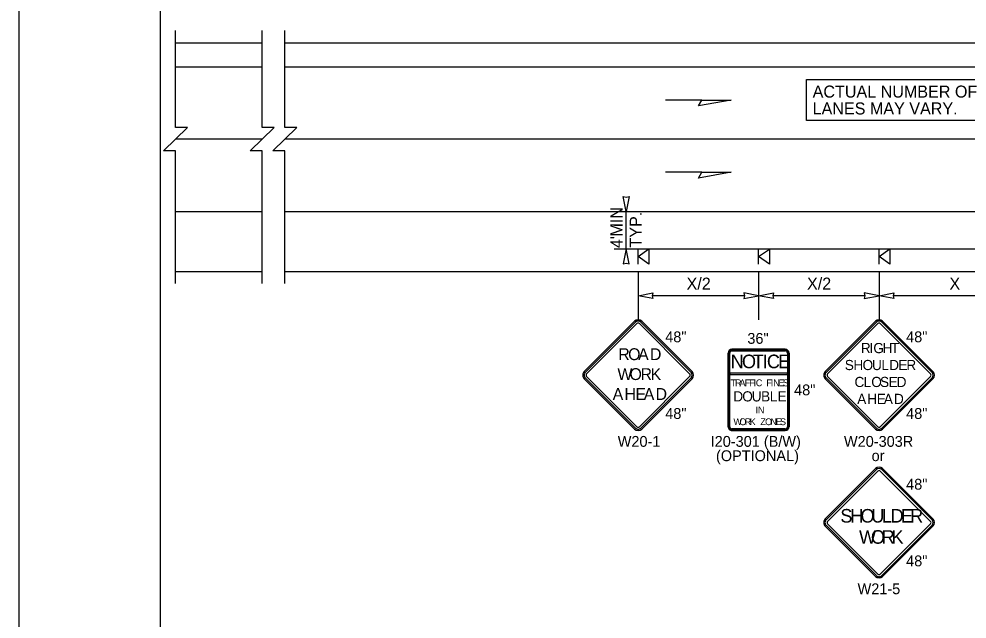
# Model space of a CAD drawing. Extents: x 99999.1 to 100055.7, y 99995 to 100013.2.
# Drawn here: x 99999.06 to 100005.36, y 100002.93 to 100006.91 of the extents above; entities that cross this region are included whole.
import ezdxf

# ---------------------------------------------------------------- set-up
doc = ezdxf.new("R2010")
doc.units = 0
for name, color, linetype in [('RD_ED_ShoulderPavedEdge', 7, 'Continuous'), ('RD_MK_LineEdgeWhite', 7, 'Continuous'), ('RD_MK_LineEdgeYellow', 7, 'Continuous'), ('RD_MK_LineLane', 7, 'Continuous'), ('SH_GI_PlotLimits', 7, 'Continuous'), ('SH_GI_SheetBorder', 7, 'Continuous'), ('SH_TI_Tables', 7, 'Continuous'), ('TR_SN_ConstructionSigns', 7, 'Continuous'), ('TR_WZ_PortableSignMountBlk-Org', 7, 'Continuous'), ('TR_WZ_PortableSignMountBlk-Wht', 7, 'Continuous'), ('TR_WZ_WorkZoneDetails', 7, 'Continuous'), ('TR_WZ_WorkZoneTextCurrent', 7, 'Continuous')]:
    doc.layers.add(name, color=color, linetype=linetype)

msp = doc.modelspace()

# ---------------------------------------------------------------- linework, layer by layer
at = {"layer": 'RD_ED_ShoulderPavedEdge'}
for p, q in [((100000.1016, 100006.7557), (100000.6783, 100006.7557)), ((100000.8283, 100006.7557), (100015.62, 100006.7557)), ((100000.1016, 100005.2357), (100000.6783, 100005.2357)), ((100000.8283, 100005.2357), (100015.62, 100005.2357))]:
    msp.add_line(p, q, dxfattribs=at)
at = {"layer": 'RD_MK_LineEdgeWhite'}
for p, q in [((100000.1016, 100005.6357), (100000.6783, 100005.6357)), ((100000.8283, 100005.6357), (100015.62, 100005.6357))]:
    msp.add_line(p, q, dxfattribs=at)
at = {"layer": 'RD_MK_LineEdgeYellow'}
for p, q in [((100000.1016, 100006.5957), (100000.6783, 100006.5957)), ((100000.8283, 100006.5957), (100015.62, 100006.5957))]:
    msp.add_line(p, q, dxfattribs=at)
at = {"layer": 'RD_MK_LineLane'}
for points in [[(100000.6783, 100006.1157), (100000.1016, 100006.1157)], [(100015.62, 100006.1157), (100000.8283, 100006.1157)]]:
    msp.add_lwpolyline(points, dxfattribs=at)
at = {"layer": 'SH_GI_PlotLimits'}
msp.add_lwpolyline([(99999.0625, 99999.6875), (100016.0625, 99999.6875), (100016.0625, 100010.6875), (99999.0625, 100010.6875)], close=True, dxfattribs=at)
at = {"layer": 'SH_GI_SheetBorder'}
msp.add_line((100000, 100010.375), (100000, 100000), dxfattribs=at)
at = {"layer": 'SH_TI_Tables'}
msp.add_lwpolyline([(100004.2941, 100006.511), (100005.5872, 100006.511), (100005.5872, 100006.239), (100004.2941, 100006.239)], close=True, dxfattribs=at)
at = {"layer": 'TR_SN_ConstructionSigns'}
for p, q in [((100003.1514, 100004.9058), (100002.8173, 100004.5717)), ((100003.1574, 100004.8999), (100002.8233, 100004.5658)), ((100002.8332, 100004.5558), (100003.1673, 100004.8899)), ((100003.1832, 100004.8899), (100003.5173, 100004.5558)), ((100003.5273, 100004.5658), (100003.1932, 100004.8999)), ((100003.5333, 100004.5717), (100003.1991, 100004.9058)), ((100004.7514, 100004.9058), (100004.4173, 100004.5717)), ((100004.7574, 100004.8999), (100004.4233, 100004.5658)), ((100004.4332, 100004.5558), (100004.7673, 100004.8899)), ((100004.7832, 100004.8899), (100005.1173, 100004.5558)), ((100005.1273, 100004.5658), (100004.7932, 100004.8999)), ((100005.1333, 100004.5717), (100004.7991, 100004.9058)), ((100003.7981, 100004.72), (100004.1525, 100004.72)), ((100004.1525, 100004.72), (100003.7981, 100004.72)), ((100004.1525, 100004.72), (100003.7981, 100004.72)), ((100004.1525, 100004.7158), (100003.7981, 100004.7158)), ((100003.7981, 100004.7088), (100004.1525, 100004.7088)), ((100003.7728, 100004.2053), (100003.7728, 100004.6947)), ((100003.7728, 100004.6947), (100003.7728, 100004.2053)), ((100003.7728, 100004.6947), (100003.7728, 100004.2053)), ((100003.777, 100004.6947), (100003.777, 100004.2053)), ((100003.784, 100004.5604), (100003.784, 100004.6947)), ((100004.1665, 100004.6947), (100004.1665, 100004.5604)), ((100004.1736, 100004.2053), (100004.1736, 100004.6947)), ((100004.1778, 100004.6947), (100004.1778, 100004.2053)), ((100004.1778, 100004.2053), (100004.1778, 100004.6947)), ((100004.1778, 100004.2053), (100004.1778, 100004.6947)), ((100002.8173, 100004.524), (100003.1514, 100004.1899)), ((100002.8233, 100004.53), (100003.1574, 100004.1959)), ((100003.1673, 100004.2058), (100002.8332, 100004.5399)), ((100003.5173, 100004.5399), (100003.1832, 100004.2058)), ((100003.1932, 100004.1959), (100003.5273, 100004.53)), ((100003.1991, 100004.1899), (100003.5333, 100004.524)), ((100003.784, 100004.5604), (100003.784, 100004.5604)), ((100004.1665, 100004.5604), (100003.784, 100004.5604)), ((100003.784, 100004.5604), (100003.784, 100004.5534)), ((100003.784, 100004.5534), (100003.784, 100004.5604)), ((100003.784, 100004.5534), (100004.1665, 100004.5534)), ((100003.784, 100004.2053), (100003.784, 100004.5534)), ((100004.1665, 100004.5534), (100004.1665, 100004.5604)), ((100004.1665, 100004.5604), (100004.1665, 100004.5534)), ((100004.1665, 100004.5534), (100004.1665, 100004.2053)), ((100004.4173, 100004.524), (100004.7514, 100004.1899)), ((100004.4233, 100004.53), (100004.7574, 100004.1959)), ((100004.7673, 100004.2058), (100004.4332, 100004.5399)), ((100005.1173, 100004.5399), (100004.7832, 100004.2058)), ((100004.7932, 100004.1959), (100005.1273, 100004.53)), ((100004.7991, 100004.1899), (100005.1333, 100004.524)), ((100004.1525, 100004.1913), (100003.7981, 100004.1913)), ((100003.7981, 100004.1842), (100004.1525, 100004.1842)), ((100004.1525, 100004.18), (100003.7981, 100004.18)), ((100003.7981, 100004.18), (100004.1525, 100004.18)), ((100003.7981, 100004.18), (100004.1525, 100004.18)), ((100004.7514, 100003.9271), (100004.4173, 100003.5929)), ((100004.7574, 100003.9211), (100004.4233, 100003.587)), ((100004.4332, 100003.577), (100004.7673, 100003.9111)), ((100004.7832, 100003.9111), (100005.1173, 100003.577)), ((100005.1273, 100003.587), (100004.7932, 100003.9211)), ((100005.1333, 100003.5929), (100004.7991, 100003.9271)), ((100004.4173, 100003.5452), (100004.7514, 100003.2111)), ((100004.4233, 100003.5512), (100004.7574, 100003.2171)), ((100004.7673, 100003.227), (100004.4332, 100003.5611)), ((100005.1173, 100003.5611), (100004.7832, 100003.227)), ((100004.7932, 100003.2171), (100005.1273, 100003.5512)), ((100004.7991, 100003.2111), (100005.1333, 100003.5452))]:
    msp.add_line(p, q, dxfattribs=at)
for centre, radius, start, end in [((100003.1753, 100004.882), 0.0338, 45, 135), ((100003.1753, 100004.882), 0.0253, 45, 135), ((100003.1753, 100004.882), 0.0113, 45, 135), ((100004.7753, 100004.882), 0.0338, 45, 135), ((100004.7753, 100004.882), 0.0253, 45, 135), ((100004.7753, 100004.882), 0.0113, 45, 135), ((100003.7981, 100004.6947), 0.0253, 90, 180), ((100003.7981, 100004.6947), 0.0253, 90, 180), ((100003.7981, 100004.6947), 0.0253, 90, 180), ((100003.7981, 100004.6947), 0.0211, 90, 180.00001), ((100003.7981, 100004.6947), 0.0141, 90, 180.00001), ((100004.1525, 100004.6947), 0.0253, 0, 90), ((100004.1525, 100004.6947), 0.0253, 0, 90), ((100004.1525, 100004.6947), 0.0253, 0, 90), ((100004.1525, 100004.6947), 0.0211, 0, 90), ((100004.1525, 100004.6947), 0.0141, 0, 90), ((100002.8412, 100004.5479), 0.0338, 135, 225.00001), ((100003.5094, 100004.5479), 0.0338, 315.00001, 45.00001), ((100004.4412, 100004.5479), 0.0338, 135, 225.00001), ((100005.1094, 100004.5479), 0.0338, 315.00001, 45.00001), ((100002.8412, 100004.5479), 0.0253, 135, 225.00001), ((100002.8412, 100004.5479), 0.0113, 135, 225.00001), ((100003.5094, 100004.5479), 0.0113, 315.00002, 45), ((100003.5094, 100004.5479), 0.0253, 315.00002, 45), ((100004.4412, 100004.5479), 0.0253, 135, 225.00001), ((100004.4412, 100004.5479), 0.0113, 135, 225.00001), ((100005.1094, 100004.5479), 0.0113, 315.00002, 45), ((100005.1094, 100004.5479), 0.0253, 315.00002, 45), ((100003.1753, 100004.2138), 0.0253, 225.00001, 315.00002), ((100003.1753, 100004.2138), 0.0113, 225.00001, 315.00002), ((100003.7981, 100004.2053), 0.0253, 180, 270.00001), ((100003.7981, 100004.2053), 0.0253, 180, 270.00001), ((100003.7981, 100004.2053), 0.0253, 180, 270.00001), ((100003.7981, 100004.2053), 0.0211, 180.00001, 270), ((100003.7981, 100004.2053), 0.0141, 180.00001, 270), ((100004.1525, 100004.2053), 0.0253, 270.00001, 0.00001), ((100004.1525, 100004.2053), 0.0253, 270.00001, 0.00001), ((100004.1525, 100004.2053), 0.0211, 270, 0.00001), ((100004.1525, 100004.2053), 0.0141, 270, 0.00001), ((100004.1525, 100004.2053), 0.0253, 270.00001, 0.00001), ((100004.7753, 100004.2138), 0.0253, 225.00001, 315.00002), ((100004.7753, 100004.2138), 0.0113, 225.00001, 315.00002), ((100003.1753, 100004.2138), 0.0338, 225.00001, 315.00001), ((100004.7753, 100004.2138), 0.0338, 225.00001, 315.00001), ((100004.7753, 100003.9032), 0.0338, 45, 135), ((100004.7753, 100003.9032), 0.0253, 45, 135), ((100004.7753, 100003.9032), 0.0113, 45, 135), ((100004.4412, 100003.5691), 0.0338, 135, 225.00001), ((100004.4412, 100003.5691), 0.0253, 135, 225.00001), ((100004.4412, 100003.5691), 0.0113, 135, 225.00001), ((100005.1094, 100003.5691), 0.0113, 315.00002, 45), ((100005.1094, 100003.5691), 0.0253, 315.00002, 45), ((100005.1094, 100003.5691), 0.0338, 315.00001, 45.00001), ((100004.7753, 100003.235), 0.0338, 225.00001, 315.00001), ((100004.7753, 100003.235), 0.0253, 225.00001, 315.00002), ((100004.7753, 100003.235), 0.0113, 225.00001, 315.00002)]:
    msp.add_arc(centre, radius, start, end, dxfattribs=at)
at = {"layer": 'TR_WZ_PortableSignMountBlk-Org'}
for p, q in [((100003.1753, 100005.2858), (100003.1753, 100005.3858)), ((100004.7753, 100005.2858), (100004.7753, 100005.3858))]:
    msp.add_line(p, q, dxfattribs=at)
for points in [[(100003.1753, 100005.3357), (100003.2471, 100005.3858), (100003.2471, 100005.2858)], [(100004.7753, 100005.3357), (100004.8471, 100005.3858), (100004.8471, 100005.2858)]]:
    msp.add_lwpolyline(points, close=True, dxfattribs=at)
at = {"layer": 'TR_WZ_PortableSignMountBlk-Wht'}
msp.add_line((100003.9753, 100005.2857), (100003.9753, 100005.3857), dxfattribs=at)
msp.add_lwpolyline([(100003.9753, 100005.3356), (100004.0471, 100005.3857), (100004.0471, 100005.2857)], close=True, dxfattribs=at)
at = {"layer": 'TR_WZ_WorkZoneDetails'}
for p, q in [((100003.5976, 100006.375), (100003.3565, 100006.375)), ((100003.5976, 100005.895), (100003.3565, 100005.895)), ((100003.0153, 100005.6357), (100003.1753, 100005.6357)), ((100003.0953, 100005.3858), (100003.0953, 100005.6357)), ((100003.0153, 100005.3858), (100003.1753, 100005.3858)), ((100003.1753, 100005.3858), (100005.7753, 100005.3858)), ((100003.1753, 100005.2357), (100003.1753, 100004.9157)), ((100003.9753, 100005.236), (100003.9753, 100004.9157)), ((100004.7753, 100005.236), (100004.7753, 100004.9157)), ((100003.8815, 100005.0757), (100003.269, 100005.0757)), ((100004.6815, 100005.0757), (100004.069, 100005.0757)), ((100005.6815, 100005.0757), (100004.869, 100005.0757))]:
    msp.add_line(p, q, dxfattribs=at)
for points in [[(100000.1016, 100005.1557), (100000.1016, 100006.0383), (100000.0216, 100006.0383), (100000.1817, 100006.1932), (100000.1016, 100006.1932), (100000.1016, 100006.8357)], [(100000.6783, 100005.1557), (100000.6783, 100006.0383), (100000.5983, 100006.0383), (100000.7583, 100006.1932), (100000.6783, 100006.1932), (100000.6783, 100006.8357)], [(100000.8283, 100005.1557), (100000.8283, 100006.0383), (100000.7483, 100006.0383), (100000.9083, 100006.1932), (100000.8283, 100006.1932), (100000.8283, 100006.8357)]]:
    msp.add_lwpolyline(points, dxfattribs=at)
for points in [[(100003.7941, 100006.375), (100003.5753, 100006.3364), (100003.5976, 100006.375)], [(100003.7941, 100005.895), (100003.5753, 100005.8564), (100003.5976, 100005.895)], [(100003.0953, 100005.6357), (100003.076, 100005.734), (100003.0953, 100005.7295), (100003.1146, 100005.734)], [(100003.0953, 100005.3858), (100003.076, 100005.2875), (100003.0953, 100005.2921), (100003.1146, 100005.2875)], [(100003.1753, 100005.0757), (100003.2736, 100005.095), (100003.269, 100005.0757), (100003.2736, 100005.0565)], [(100003.9753, 100005.0757), (100003.877, 100005.095), (100003.8815, 100005.0757), (100003.877, 100005.0565)], [(100003.9753, 100005.0757), (100004.0736, 100005.095), (100004.069, 100005.0757), (100004.0736, 100005.0565)], [(100004.7753, 100005.0757), (100004.677, 100005.095), (100004.6815, 100005.0757), (100004.677, 100005.0565)], [(100004.7753, 100005.0757), (100004.8736, 100005.095), (100004.869, 100005.0757), (100004.8736, 100005.0565)]]:
    msp.add_lwpolyline(points, close=True, dxfattribs=at)

# ---------------------------------------------------------------- texts
at = {"layer": 'SH_TI_Tables'}
for s, p in [('ACTUAL NUMBER OF', (100004.3341, 100006.391)), ('LANES MAY VARY.', (100004.3341, 100006.279))]:
    msp.add_text(s, height=0.08, rotation=360, dxfattribs=at).set_placement(p)
at = {"layer": 'TR_SN_ConstructionSigns'}
for s, p in [('48"', (100003.3551, 100004.7664)), ('36"', (100003.9005, 100004.756)), ('48"', (100004.9551, 100004.7664)), ('48"', (100004.211, 100004.414)), ('48"', (100003.3551, 100004.2573)), ('48"', (100004.9551, 100004.2573)), ('W20-1', (100003.0395, 100004.072)), ('I20-301 (B/W)', (100003.6567, 100004.072)), ('W20-303R', (100004.5422, 100004.072)), ('(OPTIONAL)', (100003.6921, 100003.9769)), ('or', (100004.7257, 100003.9769)), ('48"', (100004.9551, 100003.7876)), ('48"', (100004.9551, 100003.2785)), ('W21-5', (100004.6327, 100003.0932))]:
    msp.add_text(s, height=0.072, rotation=360, dxfattribs=at).set_placement(p)
for s, height, p in [('R', 0.0675, (100004.6545, 100004.6941)), ('I', 0.0675, (100004.7118, 100004.6941)), ('G', 0.0675, (100004.7375, 100004.6941)), ('H', 0.0675, (100004.7982, 100004.6941)), ('T', 0.0675, (100004.8543, 100004.6941)), ('R', 0.0788, (100003.0434, 100004.6477)), ('O', 0.0788, (100003.1087, 100004.6477)), ('A', 0.0788, (100003.1749, 100004.6477)), ('D', 0.0788, (100003.2536, 100004.6477)), ('N', 0.09, (100003.7895, 100004.5942)), ('O', 0.09, (100003.8646, 100004.5942)), ('T', 0.09, (100003.9367, 100004.5942)), ('I', 0.09, (100004.0019, 100004.5942)), ('C', 0.09, (100004.0302, 100004.5942)), ('E', 0.09, (100004.1052, 100004.5942)), ('S', 0.0675, (100004.5478, 100004.5816)), ('H', 0.0675, (100004.6052, 100004.5816)), ('O', 0.0675, (100004.6659, 100004.5816)), ('U', 0.0675, (100004.7287, 100004.5816)), ('L', 0.0675, (100004.7908, 100004.5816)), ('D', 0.0675, (100004.8428, 100004.5816)), ('E', 0.0675, (100004.9035, 100004.5816)), ('R', 0.0675, (100004.9569, 100004.5816)), ('W', 0.0788, (100003.0375, 100004.5155)), ('O', 0.0788, (100003.1178, 100004.5155)), ('R', 0.0788, (100003.191, 100004.5155)), ('K', 0.0788, (100003.258, 100004.5155)), ('T', 0.045, (100003.7894, 100004.4746)), ('R', 0.045, (100003.8187, 100004.4746)), ('A', 0.045, (100003.8479, 100004.4746)), ('F', 0.045, (100003.883, 100004.4746)), ('F', 0.045, (100003.9123, 100004.4746)), ('I', 0.045, (100003.9415, 100004.4746)), ('C', 0.045, (100003.9568, 100004.4746)), ('F', 0.045, (100004.027, 100004.4746)), ('I', 0.045, (100004.0563, 100004.4746)), ('N', 0.045, (100004.0725, 100004.4746)), ('E', 0.045, (100004.1076, 100004.4746)), ('S', 0.045, (100004.1359, 100004.4746)), ('C', 0.0675, (100004.6123, 100004.4691)), ('L', 0.0675, (100004.673, 100004.4691)), ('O', 0.0675, (100004.7236, 100004.4691)), ('S', 0.0675, (100004.7817, 100004.4691)), ('E', 0.0675, (100004.8391, 100004.4691)), ('D', 0.0675, (100004.8924, 100004.4691)), ('A', 0.0788, (100003.006, 100004.3833)), ('H', 0.0788, (100003.0847, 100004.3833)), ('E', 0.0788, (100003.1572, 100004.3833)), ('A', 0.0788, (100003.2123, 100004.3833)), ('D', 0.0788, (100003.291, 100004.3833)), ('D', 0.0675, (100003.8075, 100004.3734)), ('O', 0.0675, (100003.8669, 100004.3734)), ('U', 0.0675, (100003.9297, 100004.3734)), ('B', 0.0675, (100003.9918, 100004.3734)), ('L', 0.0675, (100004.0492, 100004.3734)), ('E', 0.0675, (100004.1012, 100004.3734)), ('A', 0.0675, (100004.6302, 100004.3566)), ('H', 0.0675, (100004.6977, 100004.3566)), ('E', 0.0675, (100004.7598, 100004.3566)), ('A', 0.0675, (100004.807, 100004.3566)), ('D', 0.0675, (100004.8745, 100004.3566)), ('I', 0.045, (100003.9546, 100004.2946)), ('N', 0.045, (100003.9708, 100004.2946)), ('W', 0.045, (100003.8081, 100004.2159)), ('O', 0.045, (100003.8477, 100004.2159)), ('R', 0.045, (100003.8833, 100004.2159)), ('K', 0.045, (100003.9161, 100004.2159)), ('Z', 0.045, (100003.9863, 100004.2159)), ('O', 0.045, (100004.0183, 100004.2159)), ('N', 0.045, (100004.0538, 100004.2159)), ('E', 0.045, (100004.0889, 100004.2159)), ('S', 0.045, (100004.1173, 100004.2159)), ('S', 0.09, (100004.5183, 100003.5691)), ('H', 0.09, (100004.584, 100003.5691)), ('O', 0.09, (100004.6524, 100003.5691)), ('U', 0.09, (100004.7235, 100003.5691)), ('L', 0.09, (100004.7937, 100003.5691)), ('D', 0.09, (100004.8522, 100003.5691)), ('E', 0.09, (100004.9206, 100003.5691)), ('R', 0.09, (100004.9818, 100003.5691)), ('W', 0.09, (100004.6421, 100003.4285)), ('O', 0.09, (100004.7213, 100003.4285)), ('R', 0.09, (100004.7924, 100003.4285)), ('K', 0.09, (100004.8581, 100003.4285))]:
    msp.add_text(s, height=height, dxfattribs=at).set_placement(p)
at = {"layer": 'TR_WZ_WorkZoneTextCurrent'}
for s, rotation, p in [('MIN', 90, (100003.0713, 100005.4682)), ('TYP.', 90, (100003.1993, 100005.3954)), ("4'", 90, (100003.0713, 100005.3917)), ('X/2', 360, (100003.4968, 100005.1157)), ('X/2', 360, (100004.2968, 100005.1157)), ('X', 360, (100005.2428, 100005.1157))]:
    msp.add_text(s, height=0.08, rotation=rotation, dxfattribs=at).set_placement(p)

doc.saveas('drawing.dxf')
